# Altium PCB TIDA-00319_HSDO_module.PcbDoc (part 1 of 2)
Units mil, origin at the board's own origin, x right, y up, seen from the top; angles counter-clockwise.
Board outline 6250 x 2150 mil, 2 copper layers (Component Side, Bottom Layer), stack 12.8 mil thick; 90 components, 121 nets, 306 pads, 593 vias.
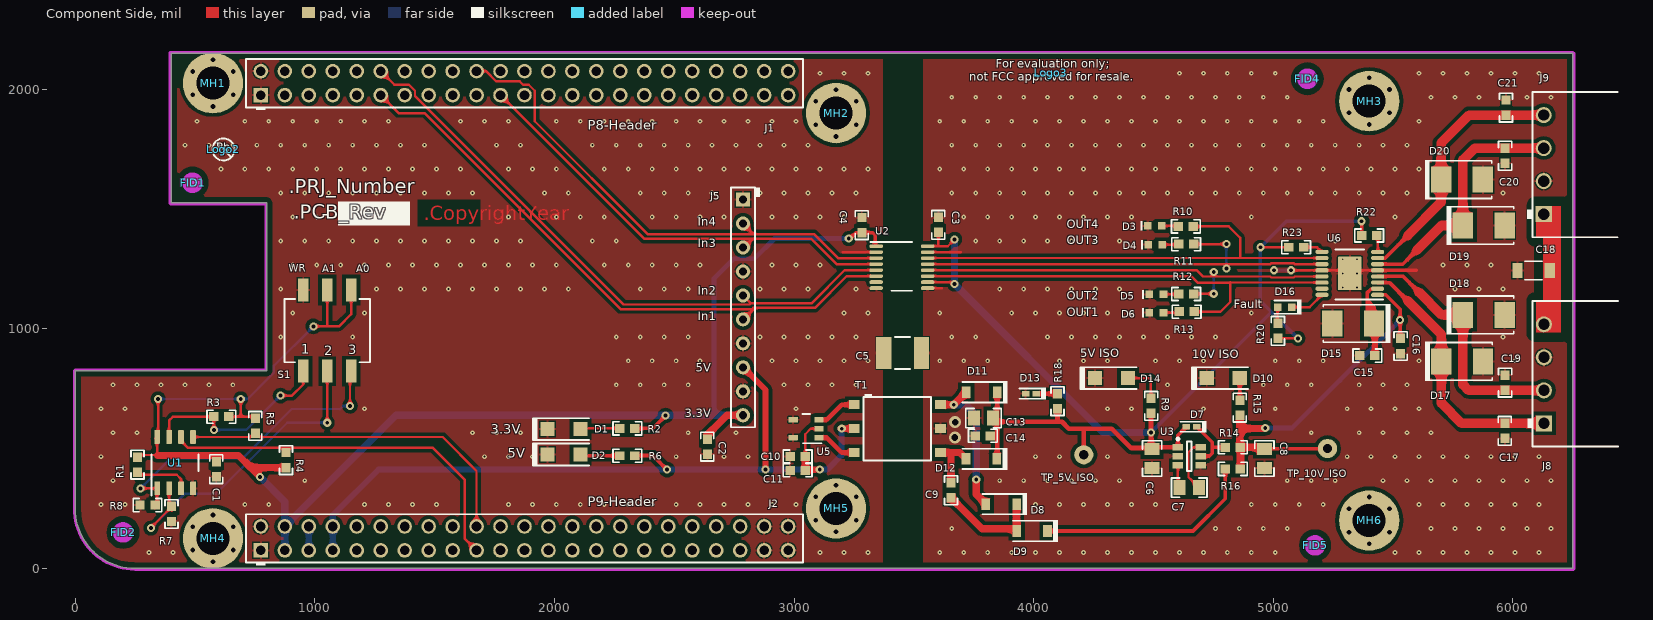
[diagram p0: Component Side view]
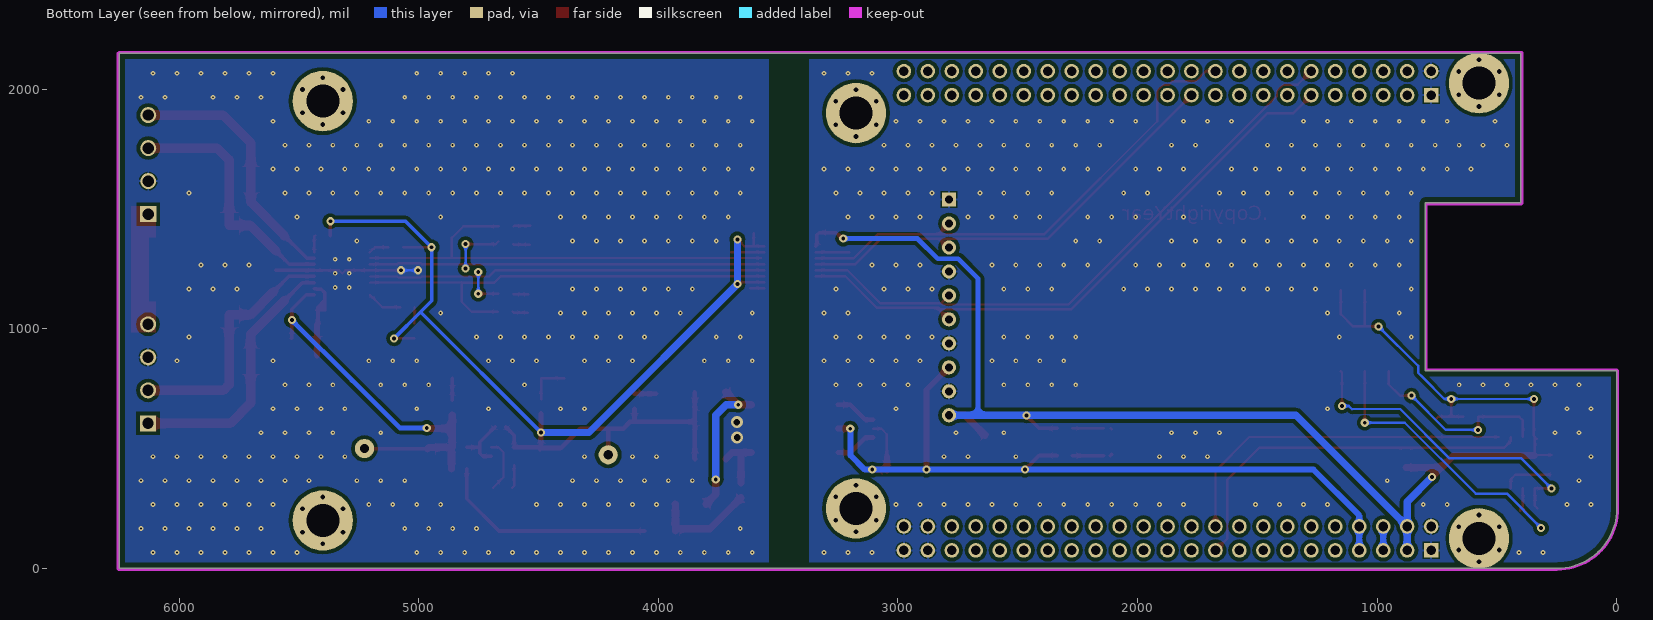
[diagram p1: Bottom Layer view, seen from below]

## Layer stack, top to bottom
Top Solder: solder mask 0.4, Solder Resist, Dk 3.5
Component Side: signal copper 1.4
Dielectric 1: core 10, FR-4, Dk 4.2
Bottom Layer: signal copper 1.4
Solder Side: solder mask 0.4, Solder Resist, Dk 3.5

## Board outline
250,0 cw(c250,250) 0,250 0,825 800,825 800,1525 400,1525 400,2150 6250,2150 6250,0

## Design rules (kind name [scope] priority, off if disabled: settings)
AcuteAngle [All] p1: minimum=3.00000000000000E+0001 checktracksonly=FALSE
AssemblyTestPointUsage [All] p1: valid=2
Clearance Clearance_1 [(ObjectKind = 'Fill') And (Net = 'EARTH')] p1: gap=40
Clearance Clearance_BoardEdge_MountingHoles [OnCopper and InComponentClass('Mounting Holes') vs IsKeepOut] p2: gap=40
Clearance Clearance_BoardEdge_Poly [OnCopper and InPoly vs IsKeepOut] p3: gap=25
Clearance Clearance_BoardEdge [OnCopper and Not InComponentClass('Logo') and not InComponentClass('FiducialMark') and not InRegion(1000,500,4000,800) and Not IsKeepout vs IsKeepOut] p4: gap=24
Clearance Clearance_Poly [InPolygon] p5: gap=15
Clearance [All] p6: gap=7.5
ComponentClearance ComponentClearance_Shunt [InComponentClass('Header') vs InComponentClass('Shunt')] p1: gap=0 collisioncheckmode=3 verticalgap=0 showdistances=FALSE
ComponentClearance ComponentClearance_MountingHoles_FiducialMarks [InComponentClass('Mounting Holes') vs InComponentClass('FiducialMark')] p2: gap=50 collisioncheckmode=3 verticalgap=10 showdistances=FALSE
ComponentClearance ComponentClearance_Logo [InComponentClass('Logo')] p3: gap=50 collisioncheckmode=3 verticalgap=10 showdistances=FALSE
ComponentClearance ComponentClearance_ScrewToNut [(HasFootprint('NY PMS 440 0025 PH')) vs (HasFootprint('Keystone_1902C'))] p4: gap=5 collisioncheckmode=3 verticalgap=10 showdistances=FALSE
ComponentClearance ComponentClearance_MountingHoles [name like 'MH*'] p5: gap=0 collisioncheckmode=3 verticalgap=100000 showdistances=FALSE
ComponentClearance ComponentClearance_SmallPassives [HasFootprint('0201*') or HasFootprint('0402*') or HasFootprint('0508') or HasFootprint('0603*') or HasFootprint('0612') or HasFootprint('0805*') or HasFootprint('0815*') or HasFootprint('0830*') or HasFootprint('1206*') or HasFootprint('1210*') or HasFootprint('1808*') or HasFootprint('1812*') or HasFootprint('1825*') or HasFootprint('2010*') or HasFootprint('2220*') or HasFootprint('2225*') or HasFootprint('2512*') or HasFootprint('2728*') or HasFootprint('3518*') vs HasFootprint('0201*') or HasFootprint('0402*') or HasFootprint('0508') or HasFootprint('0603*') or HasFootprint('0612') or HasFootprint('0805*') or HasFootprint('0815*') or HasFootprint('0830*') or HasFootprint('1206*') or HasFootprint('1210*') or HasFootprint('1808*') or HasFootprint('1812*') or HasFootprint('1825*') or HasFootprint('2010*') or HasFootprint('2220*') or HasFootprint('2225*') or HasFootprint('2512*') or HasFootprint('2728*') or HasFootprint('3518*')] p6: gap=20 collisioncheckmode=3 verticalgap=10 showdistances=FALSE
ComponentClearance ComponentClearance_THtoSMT [IsThruComponent vs IsSMTComponent] p7: gap=90 collisioncheckmode=3 verticalgap=30 showdistances=FALSE
ComponentClearance ComponentClearance_THtoTH [IsThruComponent and not name like ('J8*') vs IsThruComponent and not name like ('J8*')] p8: gap=118.11 collisioncheckmode=3 verticalgap=30 showdistances=FALSE
ComponentClearance [All] p9: gap=38 collisioncheckmode=3 verticalgap=10 showdistances=FALSE
DiffPairsRouting [All] p1: maxlimit=100 minlimit=10 mostfreqgap=10 toplayer_minwidth=15 toplayer_maxwidth=15 toplayer_prefwidth=15 bottomlayer_minwidth=15 bottomlayer_maxwidth=15 bottomlayer_prefwidth=15 maxuncoupledlength=1000
FabricationTestPointUsage TestPointUsage [All] p1: valid=2 allowmultiple=FALSE
FabricationTestpoint Testpoint [All] p1: side=3 testpointundercomponent=TRUE minsize=40 maxsize=100 preferedsize=60 minholesize=0 maxholesize=40 preferedholesize=32 testpointgrid=1 allowsidetop=TRUE allowsidebottom=TRUE usegrid=TRUE gridtolerance=0.01
FanoutControl Fanout_LCC [IsLCC] p1: bgadir=Out bgaviamode=Centered fanoutstyle=Auto fanoutdirection=Alternating viagrid=1 // Fanout_LCC (Default Rule)
FanoutControl Fanout_BGA [IsBGA] p2: bgadir=Out bgaviamode=Centered fanoutstyle=Auto fanoutdirection=Alternating viagrid=1 // Fanout_BGA (Default Rule)
FanoutControl Fanout_Default [All] p4: bgadir=Out bgaviamode=Centered fanoutstyle=Auto fanoutdirection=Alternating viagrid=1 // Fanout_Default (Default Rule)
FanoutControl Fanout_Small [(CompPinCount < 5)] p5: bgadir=Out bgaviamode=Centered fanoutstyle=Auto fanoutdirection=OutThenIn viagrid=1 // Fanout_Small (Default Rule)
HoleSize [All] p1: absolutevalues=TRUE maxlimit=251 minlimit=7.6 maxpercent=80.000 minpercent=20.000
MinimumAnnularRing MinimumAnnularRing_InPoly [All] p1: minimumring=3
MinimumAnnularRing MinimumAnnularRing_ThermalPadVias [IsVia and InAnyComponent] p2: minimumring=3
MinimumAnnularRing [All] p3: minimumring=9
MinimumSolderMaskSliver MinimumSolderMaskSliver_Logo [InComponentClass('Logo') vs InComponentClass('Logo')] p1: minsoldermaskwidth=0.7
MinimumSolderMaskSliver [All] p2: minsoldermaskwidth=3.94
PlaneClearance [All] p1: clearance=10
PlaneConnect [All] p1: planeconnectstyle=Direct reliefexpansion=15 reliefentries=4 reliefconductorwidth=10 reliefairgap=5
PolygonConnect Polygon2Via [IsVia] p1: connectstyle=Direct reliefconductorwidth=10 reliefentries=4 polygonreliefangle="90 Angle" airgapwidth=10
PolygonConnect ThermalPolygonVia [IsVia AND (ViaDiameter = '50')] p2: connectstyle=Direct reliefconductorwidth=10 reliefentries=4 polygonreliefangle="90 Angle" airgapwidth=10
PolygonConnect ThermalPolygonPad [((ObjectKind = 'Pad') And (((Name Like 'U*') or (Name Like 'D*')) and (InComponentClass('TIDA-00183_pg-4_Driver') or InComponentClass('TIDA-00183_pg-5_OP_Connector')))) or ((ObjectKind = 'Pad') And (Name like 'U61*'))] p3: connectstyle=Direct reliefconductorwidth=10 reliefentries=4 polygonreliefangle="90 Angle" airgapwidth=10
PolygonConnect [All] p4: connectstyle=Relief reliefconductorwidth=10 reliefentries=4 polygonreliefangle="90 Angle" airgapwidth=5
RoutingVias ThermalPadVias [IsVia and InAnyComponent] p1: holewidth=7.87 width=20 viastyle="Through Hole" minholewidth=7.87 minwidth=10 maxholewidth=20 maxwidth=40
RoutingVias [All] p2: holewidth=16 width=34 viastyle="Through Hole" minholewidth=7.87 minwidth=20 maxholewidth=40 maxwidth=65
SMDToCorner [All] p1: distance=0
ShortCircuit ShortCircuit_MH_Via [name like 'MH*' vs IsVia] p1: allowed=TRUE
ShortCircuit [All] p2: allowed=FALSE
SilkToSilkClearance [All] p1: silktosilkclearance=0
SilkToSolderMaskClearance SilkscreenOverComponentPads [IsPad] p1: minsilkscreentomaskgap=0 clearancetoexposedcopper=TRUE
SolderMaskExpansion [All] p1: expansion=1.97
Width [All] p1: maxlimit=100 minlimit=6 preferedwidth=10 checkconnectedcopper=TRUE
14 further rules are at their usual default settings.

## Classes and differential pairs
component class TIDA-00319_HSDO_module_Hardware: FID1 FID2 FID4 FID5 Logo2 Logo3 MH1 MH2 MH3 MH4 MH5 MH6 ZZ1 ZZ2 ZZ3 ZZ4
component class FiducialMark: FID1 FID2 FID4 FID5
component class AssemblyNote: ZZ1 ZZ2 ZZ3 ZZ4
component class TIDA-00319_HSDO_module_power: C6 C7 C8 C9 C10 C11 C13 C14 D7 D8 D9 D10 D11 D12 D13 D14 R9 R14 R15 R16 R18 T1 TP_5V_ISO TP_10V_ISO U3 U5
component class Header: J5
component class TIDA-00319_HSDO_module_BBB_connector: C1 C2 D1 D2 J1 J2 R1 R2 R3 R4 R5 R6 R7 R8 S1 U1
component class TIDA-00319_HSDO_module_isolation: C3 C4 C5 D3 D4 D5 D6 J5 R10 R11 R12 R13 U2
component class TIDA-00319_HSDO_module_singout: C15 C16 C17 C18 C19 C20 C21 D15 D16 D17 D18 D19 D20 J8 J9 R20 R22 R23 U6

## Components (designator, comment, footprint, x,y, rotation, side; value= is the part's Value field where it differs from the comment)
C1 "GRM188R71C104KA01D" 0603 589,414 r270 top
C2 "GRM188R71C104KA01D" 0603 2638,508 r270 top
C3 "06033C104KAT2A" 0603 3602,1433.5 r270 top
C4 "06033C104KAT2A" 0603 3282.57,1432.7 r270 top
C5 "1812HC222KAT1A" 1812_254 3453,899 r180 top
C6 "GRM21BR71C335KA99L" 0805_HV 4494,458 r270 top
C7 "GRM21BR71C335KA99L" 0805_HV 4649,337 r180 top
C8 "GRM21BR71C335KA99L" 0805_HV 4963,459 r270 top
C9 "C1608X5R1E335K080AC" 0603 3655,326 r90 top
C10 "C1608X7R1C105K080AC" 0603 3015,467 r180 top
C11 "C1608X5R1A106M080AC" 0603 3015,409 r180 top
C13 "C2012X5R1C226K125AC" 0805_HV 3791,627.5 r180 top
C14 "GRM188R71C104KA01D" 0603 3788,553 r180 top
C15 "06033C104KAT2A" 0603 5392,888 r180 top
C16 "06033C104KAT2A" 0603 5531,928 r270 top
C17 "CGA3E2NP01H101J080AA" 0603 5966,574 r270 top
C18 "202R18W102KV4E" 1206_190 6085.65,1243 r0 top
C19 "CGA3E2NP01H101J080AA" 0603 5967,775 r90 top
C20 "CGA3E2NP01H101J080AA" 0603 5967,1722 r270 top
C21 "CGA3E2NP01H101J080AA" 0603 5971,1923 r90 top
D1 "LTST-C150KGKT" LTST-C150_1206_Green 2039.63,581.32 r0 top
D2 "LTST-C150KGKT" LTST-C150_1206_Green 2039.63,475.32 r0 top
D3 "LB Q39G-L2N2-35-1" "LB Q39G_BLUE" 4505,1429 r180 top
D4 "LB Q39G-L2N2-35-1" "LB Q39G_BLUE" 4507,1351 r180 top
D5 "LB Q39G-L2N2-35-1" "LB Q39G_BLUE" 4512,1143 r180 top
D6 "LB Q39G-L2N2-35-1" "LB Q39G_BLUE" 4512,1067 r180 top
D7 "BZT52C5V6T-7" SOD-523 4659,591 r180 top
D8 "MBR0520LT1G" SOD-123 3865,268 r180 top
D9 "MBR0520LT1G" SOD-123 3993,156 r180 top
D10 "LTST-C150KGKT" LTST-C150_1206_Green 4791,794 r0 top
D11 "MBR0520LT1G" SOD-123 3783,735 r180 top
D12 "MBR0520LT1G" SOD-123 3782,457 r180 top
D13 "BZT52C5V6T-7" SOD-523 3988,729 r180 top
D14 "LTST-C150KGKT" LTST-C150_1206_Green 4324,794 r0 top
D15 "SMBJ36A-13-F" SMB 5333,1022 r180 top
D16 "LTST-C190CKT" LED_LTST-C190_Red 5047,1090 r0 top
D17 "SMBJ36A-13-F" SMB 5788,864 r0 top
D18 "SMBJ36A-13-F" SMB 5878,1058 r0 top
D19 "SMBJ36A-13-F" SMB 5878,1431 r0 top
D20 "SMBJ36A-13-F" SMB 5787,1622 r0 top
FID1 "Fiducial" Fiducial10-20 490,1609 r0 top
FID2 "Fiducial" Fiducial10-20 200,150 r0 top
FID4 "Fiducial" Fiducial10-20 5142,2043 r0 top
FID5 "Fiducial" Fiducial10-20 5174,96 r0 top
J1 "SSHQ-123-D-08-F-LF" Major_BBB_SSHQ-123-D-08 1875,2025 r0 top
J2 "SSHQ-123-D-08-F-LF" Major_BBB_SSHQ-123-D-08 1875,125 r0 top
J5 "800-10-010-10-001000" Mill-Max_800-10-010-10-001000 2787,1089 r270 top
J8 "1844236" Phoenix_1844236 6444.26,811.9 r180 top
J9 "1844236" Phoenix_1844236 6443.26,1684.9 r180 top
Logo2 "Pb-Free Symbol" Pb-Free_Overlay_Small 619,1748 r0 top
Logo3 "FCC disclaimer" FCC_disclaimer_stacked 4072,2069 r0 top
MH1 "MTG_Pads" MTGP_4-40_PanHead 575,2025 r0 top
MH2 "MTG_Pads" MTGP_4-40_PanHead 3175,1900 r0 top
MH3 "MTG_Pads" MTGP_4-40_PanHead 5400,1950 r0 top locked
MH4 "MTG_Pads" MTGP_4-40_PanHead 575,125 r0 top
MH5 "MTG_Pads" MTGP_4-40_PanHead 3175,250 r0 top
MH6 "MTG_Pads" MTGP_4-40_PanHead 5400,200 r0 top
R1 "CRCW06035K62FKEA" 0603 260,433 r90 top
R2 "CRCW0603453RFKEA" 0603 2304,584 r0 top
R3 "CRCW06035K62FKEA" 0603 610,633 r0 top
R4 "CRCW06035K62FKEA" 0603 880,452 r270 top
R5 "CRCW06035K62FKEA" 0603 752,595 r90 top
R6 "RC0603JR-072K2L" 0603 2304,470 r0 top
R7 "CRCW06035K62FKEA" 0603 402,227 r90 top
R8 "CRCW06035K62FKEA" 0603 302,264 r0 top
R9 "RC0603JR-072K2L" 0603 4490,678 r270 top
R10 "RC0603JR-072K2L" 0603 4635,1427 r0 top
R11 "RC0603JR-072K2L" 0603 4636,1353 r0 top
R12 "RC0603JR-072K2L" 0603 4636,1145 r0 top
R13 "RC0603JR-072K2L" 0603 4638,1071 r0 top
R14 "ERJ-L03KF10CV" 0603 4831,505 r0 top
R15 "RC0603JR-072K2L" 0603 4860,671 r270 top
R16 "ERJ-L03KF10CV" 0603 4831,415 r0 top
R18 "CRCW060322R0JNEA" 0603 4099,698 r270 top
R20 "RC0603JR-073K9L" 0603 5019,991 r90 top
R22 "RC0603JR-073K9L" 0603 5400,1388.98 r180 top
R23 "RC0603JR-073K9L" 0603 5095,1339.98 r180 top
S1 "219-3MST" SW_219-3MST 1052,992 r90 top
T1 "760390012" Wurth_760390012 3431,583 r0 top
TP_5V_ISO "TESTPOINT" TESTPOINT 4209,474 r90 top
TP_10V_ISO "TESTPOINT" TESTPOINT 5226,500 r90 top
U1 "CAT24C256WI-G" SOIC-8 417,441 r90 top
U2 "ISO7140CCDBQR" DBQ0016A_N 3450,1257 r0 top
U3 "LM2765M6" MF06A_N 4649,468 r0 top
U5 "SN6501QDBVRQ1" DBV0005A_N 3050,583 r180 top
U6 "DRV8803PWPR" PWP0016D_N 5319,1231 r180 top
ZZ1 "This Assembly Note is for PCB labels only" AssemblyNoteLabel 185,3938 r0 top
ZZ2 "These assemblies are ESD sensitive, ESD precautions shall be observed." AssemblyNote 185,3829.11 r0 top
ZZ3 "These assemblies must be clean and free from flux and all contaminants. Use of no clean flux is not acceptable." AssemblyNote 185,3740.56 r0 top
ZZ4 "These assemblies must comply with workmanship standards IPC-A-610 Class 2, unless otherwise specified." AssemblyNote 185,3652 r0 top

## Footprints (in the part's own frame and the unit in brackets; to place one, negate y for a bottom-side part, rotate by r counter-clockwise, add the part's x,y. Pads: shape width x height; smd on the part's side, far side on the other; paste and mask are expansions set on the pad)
0603 [mm] "0603 from SM-752 data"
  rect 1x0.95 smd: 1(-0.8,0) 2(0.8,0)
  silkscreen extent -1.52,-0.69 1.52,0.69, body extent -0.87,-0.47 0.87,0.47, height 1
0805_HV [mil] "0805 with 30mil clearance between pads"
  rect 50x63 smd: 1(-40,0) 2(40,0)
  silkscreen extent -74,-40 74,40, body extent -43,-29 43,29, height 57
1206_190 [mm] "1206_190"
  rect 1.1x1.6 smd: 1(-1.7,0) 2(1.7,0)
  silkscreen extent -0.9,-1 0.9,1, body extent -1.75,-0.95 1.75,0.95, height 1.9
1812_254 [mm] "SMD, 2-Leads, Body 4.8x3.4mm"
  rect 1.6x3.4 smd: 1(-2,0) 2(2,0)
  silkscreen extent -0.8,-1.7 0.8,1.7, body extent -2.4,-1.7 2.4,1.7, height 2.54
AssemblyNote [mil] "Assembly Note"
AssemblyNoteLabel [mil] "Assembly Note for PCB Labels"
DBQ0016A_N [mm] "SOP, 16-Leads, Body 4.9x3.9mm, Pitch 0.635mm, IPC Medium Density"
  oval 1.45x0.4 smd: 1(-2.725,2.222) 2(-2.725,1.587) 3(-2.725,0.953) 4(-2.725,0.318) 5(-2.725,-0.318) 6(-2.725,-0.953) 7(-2.725,-1.587) 8(-2.725,-2.222) 9(2.725,-2.222) 10(2.725,-1.587) 11(2.725,-0.953) 12(2.725,-0.318) 13(2.725,0.318) 14(2.725,0.953) 15(2.725,1.587) 16(2.725,2.222)
  silkscreen extent -3.35,-2.5 1.1,2.68, body extent -3.01,-2.45 3.01,2.45, height 1.63
DBV0005A_N [mm] "SOT23, 5-Leads, Body 2.9x1.6mm, Pitch 0.95mm, Lead Span 2.8mm, IPC Medium Density"
  rrect17% 1x0.6 smd: 1(-1.375,0.95) 2(-1.375,0) 3(-1.375,-0.95) 4(1.375,-0.95) 5(1.375,0.95)
  silkscreen extent -1.63,-1.55 0.38,1.55, body extent -1.42,-1.46 1.42,1.46, height 1.09
FCC_disclaimer_stacked [mil]
Fiducial10-20 [mm]
  round 1 smd mask+0.5: 1(0,0)
  Component Side keep-out circle w1.178: c0,0 r0.5
"LB Q39G_BLUE" [mm] "OSRAM"
  rect 0.8x0.8 smd: 1(-0.75,0) 2(0.75,0)
  silkscreen extent 1.3,-0.5 1.52,0.5, body extent -0.85,-0.45 0.85,0.45, height 0.4
LED_LTST-C190_Red [mm] "Lite-On"
  rect 0.8x0.8 smd: 1(-0.75,0) 2(0.75,0)
  silkscreen extent -1.1,-0.8 1.8,0.8, body extent -0.85,-0.45 0.85,0.45, height 0.9
LTST-C150_1206_Green [mm] "SMD, 2-Leads, Body 1.6x3.2mm"
  rect 1.5x1.5 smd: 1(-1.75,0) 2(1.75,0)
  silkscreen extent -3.3,-1.15 2.65,1.15, body extent -1.65,-0.85 1.65,0.85, height 1.2
Major_BBB_SSHQ-123-D-08 [mm] "Female Connector, 2.54mm, 23x2, TH"
  rect 1.55x1.55 hole 1.02: 1(-27.94,-1.27)
  round 1.55 hole 1.02: 2(-27.94,1.27) 3(-25.4,-1.27) 4(-25.4,1.27) 5(-22.86,-1.27) 6(-22.86,1.27) 7(-20.32,-1.27) 8(-20.32,1.27) 9(-17.78,-1.27) 10(-17.78,1.27) 11(-15.24,-1.27) 12(-15.24,1.27) 13(-12.7,-1.27) 14(-12.7,1.27) 15(-10.16,-1.27) 16(-10.16,1.27) 17(-7.62,-1.27) 18(-7.62,1.27) 19(-5.08,-1.27) 20(-5.08,1.27) 21(-2.54,-1.27) 22(-2.54,1.27) 23(0,-1.27) 24(0,1.27) 25(2.54,-1.27) 26(2.54,1.27) 27(5.08,-1.27) 28(5.08,1.27) 29(7.62,-1.27) 30(7.62,1.27) 31(10.16,-1.27) 32(10.16,1.27) 33(12.7,-1.27) 34(12.7,1.27) 35(15.24,-1.27) 36(15.24,1.27) 37(17.78,-1.27) 38(17.78,1.27) 39(20.32,-1.27) 40(20.32,1.27) 41(22.86,-1.27) 42(22.86,1.27) 43(25.4,-1.27) 44(25.4,1.27) 45(27.94,-1.27) 46(27.94,1.27)
  silkscreen extent -29.53,-2.85 29.53,2.57, body extent -29.46,-2.51 29.46,2.51, height 8.51
MF06A_N [mm] "SOT23, 6-Leads, Body 2.9x1.6mm, Pitch 0.95mm, Lead Span 2.8mm, IPC Medium Density"
  rect 1.1x0.65 smd: 1(-1.2,0.95) 2(-1.2,0) 3(-1.2,-0.95) 4(1.2,-0.95) 5(1.2,0) 6(1.2,0.95)
  silkscreen extent -1.32,-1.55 0.25,1.95, body extent -0.9,-1.55 0.9,1.55, height 1.22
Mill-Max_800-10-010-10-001000 [mm] "Mill-Max"
  rect 1.5x1.5 hole 0.85: 1(-11.43,0)
  round 1.5 hole 0.85: 2(-8.89,0) 3(-6.35,0) 4(-3.81,0) 5(-1.27,0) 6(1.27,0) 7(3.81,0) 8(6.35,0) 9(8.89,0) 10(11.43,0)
  silkscreen extent -12.7,-1.27 12.7,1.78, body extent -12.7,-1.27 12.7,1.27, height 8.13
MTGP_4-40_PanHead [mm] "4-40 Mounting Hole, Plated, for Pan Head"
  round 6.4 hole 3.5: 1(0,0)
Pb-Free_Overlay_Small [mil]
  silkscreen extent -46,-46 46,46
Phoenix_1844236 [mm] "Terminal Block, 4x1, 3.5mm, R/A, TH"
  rect 1.7x1.7 hole 1.2: 1(8,5.25)
  round 1.7 hole 1.2: 2(8,1.75) 3(8,-1.75) 4(8,-5.25)
  silkscreen extent 0.15,-7.7 9.75,7.7, body extent 0,-7.7 9.2,7.7, height 7.26
PWP0016D_N [mm] "TSOP, 16-Leads, Body 5x4.4mm, Pitch 0.65mm, Exposed Pad, IPC Medium Density"
  rrect100% 1.4x0.45 smd: 1(-2.95,2.275) 2(-2.95,1.625) 3(-2.95,0.975) 4(-2.95,0.325) 5(-2.95,-0.325) 6(-2.95,-0.975) 7(-2.95,-1.625) 8(-2.95,-2.275) 9(2.95,-2.275) 10(2.95,-1.625) 11(2.95,-0.975) 12(2.95,-0.325) 13(2.95,0.325) 14(2.95,0.975) 15(2.95,1.625) 16(2.95,2.275)
  rrect4% 2.46x3.55 smd: 17(0,0)
  silkscreen extent -3.55,-2.55 1.5,2.75, body extent -3.21,-2.5 3.21,2.5, height 1
SMB [mil] "Molded Diode, 2-Leads, Body 5.4x3.6mm, IPC Medium Density, based on OnSemi component dimensions"
  rect 85x107.99 smd: 1(-87.01,0) 2(87.01,0)
  silkscreen extent -155,-82 125,82, body extent -106,-71 106,71, height 91
SOD-123 [mm] "On Semi recommended land pattern"
  rect 0.915x1.22 smd: 1(-1.637,0) 2(1.637,0)
  silkscreen extent -2.74,-1.17 2.03,1.17, body extent -1.93,-0.9 1.93,0.9, height 1.35
SOD-523 [mm] "NXP Semiconductor recommended land pattern, nominal STEP model"
  rect 0.8x0.6 smd paste-0.05: 1(-0.55,0) 2(0.55,0)
  silkscreen extent -1.6,-0.64 1.2,0.63, body extent -0.8,-0.4 0.8,0.4, height 0.72
SOIC-8 [mm] "duplicate of SO-8.  SOIC, 8-Leads, Body 5.0x4.0mm (max), Pitch 1.27mm, IPC Medium Density"
  rrect17% 1.45x0.6 smd: 1(-2.725,1.905) 2(-2.725,0.635) 3(-2.725,-0.635) 4(-2.725,-1.905) 5(2.725,-1.905) 6(2.725,-0.635) 7(2.725,0.635) 8(2.725,1.905)
  silkscreen extent -3.5,-2.5 0.9,2.5, body extent -3,-2.45 3,2.45, height 1.63
SW_219-3MST [mm] "SMD, 6-Leads, Body 6.7x9.09mm, Pitch 2.54mm"
  rect 2.44x1.13 smd: 1(-4.3,2.54) 2(-4.3,0) 3(-4.3,-2.54) 4(4.3,-2.54) 5(4.3,0) 6(4.3,2.54)
  silkscreen extent -3.35,-4.54 3.35,4.54, body extent -4.95,-4.55 4.96,4.55, height 4.3
TESTPOINT [mil]
  round 80 hole 37.99: 1(0,0)
Wurth_760390012 [mm] "SMD, 6-Leads, Body 7.14x6.73mm, Pitch 2.54mm"
  rect 1.12x0.96 smd: 1(-4.57,2.54) 2(-4.57,0) 3(-4.57,-2.54) 4(4.57,-2.54) 5(4.57,0) 6(4.57,2.54)
  silkscreen extent -3.57,-3.36 3.57,3.7, body extent -5.02,-3.36 5.02,3.36, height 4.2

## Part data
C1 C2 C14: "CAP, CERM, 0.1 µF, 16 V, +/- 10%, X7R, 0603"
C3 C4 C15 C16: "CAP, CERM, 0.1 µF, 25 V, +/- 10%, X7R, 0603"
C5: "CAP, CERM, 2200 pF, 3000 V, +/- 10%, X7R, 1812"
C6 C7 C8: "CAP, CERM, 3.3 µF, 16 V, +/- 10%, X7R, 0805"
C9: "CAP, CERM, 3.3 µF, 25 V, +/- 10%, X5R, 0603"
C10: "CAP, CERM, 1 µF, 16 V, +/- 10%, X7R, 0603"
C11: "CAP, CERM, 10 µF, 10 V, +/- 20%, X5R, 0603"
C13: "CAP, CERM, 22 µF, 16 V, +/- 10%, X5R, 0805"
C17 C19 C20 C21: "CAP, CERM, 100 pF, 50 V, +/- 5%, C0G/NP0, AEC-Q200 Grade 0, 0603"
C18: "CAP, CERM, 1000 pF, 2000 V, +/- 10%, X7R, 1206_190"
D1 D2 D10 D14: "LED, Green, SMD"
D3 D4 D5 D6: "LED, Blue, SMD"
D7 D13: "Diode, Zener, 5.6 V, 300 mW, SOD-523"
D8 D9 D11 D12: "Diode, Schottky, 20 V, 0.5 A, SOD-123"
D15 D17 D18 D19 D20: "Diode, TVS, Uni, 36 V, 600 W, SMB"
D16: "LED, Red, SMD"
FID1 FID2 FID4 FID5: "Fiducial mark.  There is nothing to buy or mount."
J1 J2: "Female Connector, 2.54mm, 23x2, TH"
J5: "Header, 100mil, 10x1, TH"
J8 J9: "Terminal Block, 4x1, 3.5mm, Green, R/A, TH"
Logo2: library part Pb-Free
Logo3: library part FCC_disclaimer, "FCC_disclaimer"
MH1 MH2 MH3 MH4 MH5 MH6: library part "Mounting Hole (Imperial) with Pads", "PCB Mounting Hole"
R1 R3 R4 R5 R7 R8: "RES, 5.62 k, 1%, 0.1 W, 0603"
R2: "RES, 453, 1%, 0.1 W, 0603"
R6 R9 R10 R11 R12 R13 R15: "RES, 2.2 k, 5%, 0.1 W, 0603"
R14 R16: "RES, 0.1, 1%, 0.1 W, 0603"
R18: "RES, 22, 5%, 0.1 W, 0603"
R20 R22 R23: "RES, 3.9 k, 5%, 0.1 W, 0603"
S1: "Switch, SPST, Slide, Off-On, 3 Pos, 0.1A, 20V, SMD"
T1: "Transformer, 475 uH, SMT"
TP_5V_ISO TP_10V_ISO: "TEST POINT.  No entry in BOM."
U1: "256 kb I2C CMOS Serial EEPROM, SOIC-8"
U2: "4242-VPK Small-Footprint and Low-Power Quad Channels Digital Isolators, DBQ0016A"
U3: "Switched Capacitor Voltage Converter, 6-pin SOT-23"
U5: "Transformer Driver for Isolated Power Supplies, DBV0005A"
U6: "Quad Low-Side Driver IC, PWP0016D"
ZZ1: library part AssemblyNoteLabel
ZZ2 ZZ3 ZZ4: library part AssemblyNote

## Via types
v1: diameter 20, hole 8, Component Side to Bottom Layer, tented both sides, 517 vias
v2: diameter 39.37, hole 19.68, Component Side to Bottom Layer, 36 vias
v3: diameter 34, hole 16, Component Side to Bottom Layer, 32 vias
v4: diameter 19.68, hole 7.87, Component Side to Bottom Layer, 6 vias
v5: diameter 50, hole 28, Component Side to Bottom Layer, 2 vias

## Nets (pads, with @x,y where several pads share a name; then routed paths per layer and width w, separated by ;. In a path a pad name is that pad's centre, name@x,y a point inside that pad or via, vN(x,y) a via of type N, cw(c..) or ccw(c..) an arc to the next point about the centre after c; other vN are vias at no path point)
AIN0: J2.39
AIN1: J2.40
AIN2: J2.37
AIN3: J2.38
AIN4: J2.33
AIN5: J2.36
AIN6: J2.35
CLKOUT2: J2.41
DGND: C1.2 C2.2 C4.1 C5.2 C10.2 C11.2 D1.1 D2.1 J1.1 J1.2 J2.1 J2.2 J2.43 J2.44 J2.45 J2.46 J5.1 J5.4 J5.7 J5.9 R7.1 R8.1 S1.6 U1.4 U2.2 U2.8 U5.4 U5.5 | length 140.2
  Component Side w10: 3202.5,1319.5 U2.2@3342.72,1319.5
  other v1: 308,66 408,66 3108,66 3208,66 3308,66 108,266 208,266 708,266 808,266 1208,266 1308,266 1408,266 1508,266 1808,266 1908,266 2008,266 2108,266 2208,266 2308,266 2408,266 2508,266 2608,266 2708,266 2808,266 2908,266 3008,266 158,366 958,366 108,466 1708,466 1808,466 1908,466 2508,466 2708,466 2808,466 158,566 258,566 1658,566 1758,566 1858,566 2558,566 2758,566 108,666 208,666 1208,666 3008,666 158,766 258,766 358,766 458,766 558,766 658,766 2258,766 2358,766 2458,766 2558,766 2958,766 3058,766 3158,766 3258,766 2308,866 2408,866 2508,866 2608,866 2908,866 3008,866 3108,866 3208,866 3308,866 858,966 1158,966 2258,966 2358,966 2458,966 2558,966 2858,966 2958,966 3058,966 3158,966 3258,966 908,1066 1208,1066 3208,1066 3308,1066 858,1166 1258,1166 1358,1166 1458,1166 1558,1166 1658,1166 1758,1166 1858,1166 1958,1166 2058,1166 2358,1166 2458,1166 2558,1166 2858,1166 2958,1166 3058,1166 3258,1166 908,1266 1008,1266 1108,1266 1208,1266 1308,1266 1408,1266 1508,1266 1608,1266 1708,1266 1808,1266 1908,1266 2008,1266 2208,1266 2308,1266 2408,1266 2508,1266 2608,1266 2908,1266 3008,1266 3108,1266 858,1366 958,1366 1058,1366 1158,1366 1258,1366 1358,1366 1458,1366 1558,1366 1658,1366 1758,1366 1858,1366 2158,1366 2258,1366 908,1466 1008,1466 1108,1466 1208,1466 1308,1466 1808,1466 2008,1466 2108,1466 2208,1466 2408,1466 2508,1466 2608,1466 2708,1466 2908,1466 3008,1466 3108,1466 3208,1466 858,1566 958,1566 1058,1566 1158,1566 1258,1566 1358,1566 1458,1566 1558,1566 1658,1566 1958,1566 2058,1566 2358,1566 2458,1566 2558,1566 2658,1566 2858,1566 2958,1566 3058,1566 3158,1566 3258,1566 608,1666 708,1666 808,1666 908,1666 1008,1666 1108,1666 1208,1666 1308,1666 1408,1666 1508,1666 1608,1666 1808,1666 1908,1666 2008,1666 2208,1666 2308,1666 2408,1666 2508,1666 2608,1666 2708,1666 2808,1666 2908,1666 3008,1666 3108,1666 3208,1666 3308,1666 458,1766 558,1766 658,1766 758,1766 858,1766 958,1766 1058,1766 1158,1766 1258,1766 1358,1766 1458,1766 1758,1766 1858,1766 2158,1766 2258,1766 2358,1766 2458,1766 2558,1766 2658,1766 2758,1766 2858,1766 2958,1766 3058,1766 508,1866 708,1866 808,1866 908,1866 1008,1866 1108,1866 1208,1866 1308,1866 1608,1866 1708,1866 1808,1866 2008,1866 2108,1866 2208,1866 2308,1866 2408,1866 2508,1866 2608,1866 2708,1866 2808,1866 2908,1866 3008,1866 3108,2066 3208,2066 3308,2066
EARTH: C18.2 J8.4 J9.1
EHRPWM1A: J2.14
EHRPWM1B: J2.16
EHRPWM2A: J1.19
EHRPWM2B: J1.13
GND_ISO: C3.1 C5.1 C6.2 C8.2 C13.2 C14.2 C15.2 C16.2 C17.2 C18.1 C19.2 C20.2 C21.2 D3.2 D4.2 D5.2 D6.2 D10.1 D13.2 D14.1 D15.2 D17.2 D18.2 D19.2 D20.2 J8.3 J9.2 T1.5 U2.9 U2.15 U3.2 U3.4 U6.5 U6.12 U6.17 | length 799.3
  Component Side w10: U2.9@3557.28,1169.5 3615.5,1169.5 ; U2.15@3557.28,1319.5 3695,1320 ; v3(5073.2,1243.8) U6.12@5202.86,1243.8 5306.2,1243.8 U6.17@5319,1231 5331.8,1243.8 U6.5@5435.14,1243.8
  Component Side w15: U6.5@5435.14,1243.8 5596,1244
  Bottom Layer w10: v3(5003.2,1243.8) v3(5073.2,1243.8)
  other v1: 3608,66 3708,66 3808,66 3908,66 4008,66 4108,66 4208,66 4308,66 4408,66 4508,66 4608,66 4708,66 4808,66 4908,66 5008,66 5508,66 5608,66 5708,66 5808,66 5908,66 6008,66 6108,66 3658,166 4758,166 4858,166 4958,166 5058,166 5658,166 5758,166 5858,166 5958,166 6058,166 6158,166 4008,266 4108,266 4208,266 4308,266 4408,266 4508,266 4908,266 5008,266 5108,266 5208,266 5608,266 5708,266 5808,266 5908,266 6008,266 6108,266 3858,366 3958,366 4058,366 4158,366 4258,366 4358,366 5058,366 5158,366 5258,366 5458,366 5558,366 5658,366 5758,366 5858,366 5958,366 6058,366 6158,366 4008,466 4108,466 4308,466 5308,466 5408,466 5508,466 5608,466 5708,466 5808,466 5908,466 6008,466 6108,466 5158,566 5358,566 5458,566 5558,566 5658,566 4308,666 4408,666 4708,666 5008,666 5308,666 5408,666 5508,666 5608,666 4558,766 4958,766 5058,766 5158,766 5358,766 5458,766 5558,766 3608,866 3708,866 3808,866 4108,866 4208,866 4308,866 4508,866 4608,866 4708,866 5008,866 5108,866 5208,866 5608,866 6008,866 3658,966 3758,966 4058,966 4158,966 4258,966 4358,966 4458,966 4558,966 4658,966 4758,966 5958,966 3608,1066 3908,1066 4008,1066 4108,1066 4208,1066 4308,1066 4408,1066 4908,1066 3858,1166 3958,1166 4058,1166 4158,1166 4258,1166 4358,1166 5758,1166 5858,1166 5958,1166 5708,1266 5808,1266 5908,1266 3758,1366 3858,1366 3958,1366 4058,1366 4158,1366 4258,1366 4358,1366 5258,1366 3708,1466 3808,1466 3908,1466 4008,1466 4108,1466 4208,1466 4308,1466 4408,1466 4908,1466 5508,1466 3658,1566 3758,1566 3858,1566 3958,1566 4058,1566 4158,1566 4258,1566 4358,1566 4458,1566 4558,1566 4658,1566 4758,1566 4858,1566 4958,1566 5058,1566 5158,1566 5258,1566 5358,1566 5458,1566 5558,1566 5958,1566 3608,1666 3708,1666 3808,1666 3908,1666 4008,1666 4108,1666 4208,1666 4308,1666 4408,1666 4508,1666 4608,1666 4708,1666 4808,1666 4908,1666 5008,1666 5108,1666 5208,1666 5308,1666 5408,1666 5508,1666 5608,1666 3658,1766 3758,1766 3858,1766 3958,1766 4058,1766 4158,1766 4258,1766 4358,1766 4458,1766 4558,1766 4658,1766 4758,1766 4858,1766 4958,1766 5058,1766 5158,1766 5258,1766 5358,1766 5458,1766 5558,1766 3608,1866 3708,1866 3808,1866 3908,1866 4008,1866 4108,1866 4208,1866 4308,1866 4408,1866 4508,1866 4608,1866 4708,1866 4808,1866 4908,1866 5008,1866 5108,1866 5208,1866 5608,1866 3658,1966 3758,1966 3858,1966 3958,1966 4058,1966 4158,1966 4258,1966 4358,1966 4458,1966 4558,1966 4658,1966 4758,1966 4858,1966 4958,1966 5058,1966 5658,1966 5758,1966 5858,1966 6058,1966 6158,1966 4608,2066 4708,2066 4808,2066 4908,2066 5008,2066 5608,2066 5708,2066 5808,2066 5908,2066 6008,2066 6108,2066
  other v4: 5289.47,1171.94 5348.53,1171.94 5289.47,1231 5348.53,1231 5289.47,1290.06 5348.53,1290.06
  other v5: 3671,546 3672,610
GNDA_ADC: J2.34
GPIO0_7: J2.42
GPIO0_26: J1.14
GPIO0_27: J1.17
GPIO1_14: J1.16
GPIO1_15: J1.15
GPIO1_16: J2.15
GPIO1_17: J2.23
GPIO1_28: J2.12
GPIO1_29: J1.26
GPIO2_1: J1.18
GPIO3_19: J2.27
GPIO3_21: J2.25
I2C2_SCL: J2.19 R4.1 U1.6 | length 1582.7
  Component Side w10: U1.6@442,548.28 442,532 471,503 1493,503 1625,371 1625,125 J2.19@1675,75
I2C2_SDA: J2.20 R5.1 U1.5 | length 1473.5
  Component Side w10: U1.5@492,548.28 1533.72,548.28 1675,407 J2.20@1675,175
INA: J1.11 J5.6 U2.6 | length 2564.4
  Component Side w10: J1.11@1275,1975 1350,1900 1458,1900 2276,1082 2824.75,1082 2829.75,1087 2837,1087 ; J5.6@2787,1039 2789,1039 2837,1087 ; U2.6@3342.72,1219.5 3219.5,1219.5 3087,1087 2837,1087
INB: J1.12 J5.5 U2.5 | length 2590
  Component Side w10: J1.12@1275,2075 1331.99,2018.01 1392.82,2018.01 1418.01,1992.82 1418.01,1971.16 2288.17,1101 2815,1101 2820,1106 ; J5.5@2787,1139 2820,1106 ; U2.5@3342.72,1244.5 3211.5,1244.5 3073,1106 2820,1106
INC: J1.21 J5.3 U2.4 | length 1917.3
  Component Side w10: J1.21@1775,1975 2374,1376 2829,1376 ; J5.3@2787,1339 2792,1339 2829,1376 ; U2.4@3342.72,1269.5 3177.5,1269.5 3071,1376 2829,1376
IND: J1.20 J5.2 U2.3 | length 2127.5
  Component Side w10: J1.20@1675,2075 1714.17,2075 1757.18,2031.99 1855.49,2031.99 1869.47,2018.01 1892.82,2018.01 1918.01,1992.82 1918.01,1865.99 2389,1395 2831,1395 ; J5.2@2787,1439 2831,1395 ; U2.3@3342.72,1294.5 3183.5,1294.5 3083,1395 2831,1395
LCD_DATA0: J1.45
LCD_DATA1: J1.46
LCD_DATA2: J1.43
LCD_DATA3: J1.44
LCD_DATA4: J1.41
LCD_DATA5: J1.42
LCD_DATA6: J1.39
LCD_DATA7: J1.40
LCD_DATA8: J1.37
LCD_DATA9: J1.38
LCD_DATA10: J1.36
LCD_DATA11: J1.34
LCD_DATA12: J1.35
LCD_DATA13: J1.33
LCD_DATA14: J1.31
LCD_DATA15: J1.32
LCD_DE: J1.30
LCD_HSYNC: J1.29
LCD_PCLK: J1.28
LCD_VSYNC: J1.27
MMC1_DAT0: J1.25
